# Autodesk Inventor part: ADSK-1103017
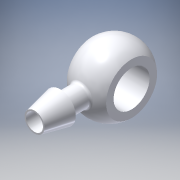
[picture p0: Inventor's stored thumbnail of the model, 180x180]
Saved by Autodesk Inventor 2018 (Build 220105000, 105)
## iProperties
Shininess: 50.0
Length Units: 11272
Angle Units: 11279
Time Units: 11290
Mass Units: 11286
Length Display Precision: 4
Angle Display Precision: 2
Compacted: True
Created: 2000-09
Part Number: ADSK-1103017
Document SubType Name: Modeling
Description: AIR INTAKE
Mass: 0.433217 g
Surface Area: 3.22275 cm^2
Volume: 0.159859 cm^3
Density: 2.71 g/cm^3
Material: Aluminum-6061
Appearance: Aluminum - Flat
Density: 0.0
Volumn: 0.0
Area: 0.0
PropertySet Name: Model Information
Control State: 0
Master: False
Checked Out: False
Author: Autodesk, Inc.
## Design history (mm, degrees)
node "Revolution1" dims "d5" = 90 deg
  sketch "Sketch2"
    geometry: L1 (-0.521, -2.783)-(-5.347, -2.783); L2 (-5.347, -2.783)-(-5.347, 0.351); L3 (-0.521, -2.783)-(-0.521, 0.351); A1 r 3.429 centre (-2.934, -2.085) between (-0.521, 0.351) and (-5.347, 0.351); 1 further point
    constraints: 6 end point, 2 parallel, 2 point on circle, 1 centre point, 1 horizontal, 1 midpoint, 1 perpendicular, 1 vertical alignment
    dimensions: "d2" = 4.1275 dimension on A1 L1; "d3" = 4.826 distance of L1.start L1.end; "d4" = 3.429 radius of A1
workaxis "Work Axis1"
workplane "Work Plane1"
node "Extrusion4" dims "d17" = 0, "d18" = 6.35
  sketch "Sketch6"
    geometry: C1 r 1.27 at (1.587, 1.923); 1 further point
    constraints: 1 centre point, 1 coincident
    dimensions: "d19" = 2.54 diameter of C1
node "Extrusion5" dims "d20" = -12 deg, "d21" = 3.175
  sketch "Sketch7"
    geometry: C1 r 1.27 at (0, 0) reference; C2 r 1.905 at (0, 0)
    constraints: 1 centre point, 1 coincident
    dimensions: "d22" = 3.81 diameter of C2
node "Extrusion6" dims "d23" = 0, "d24" = 10.795
  sketch "Sketch8"
    geometry: C1 r 1.23 at (0, 0) reference; C2 r 1.048 at (0, 0)
    constraints: 1 centre point, 1 coincident
    dimensions: "d25" = 2.0955 diameter of C2
node "Fillet2" dims "d26" = 0.381
node "Extrusion7" dims "d27" = 25.4, "d28" = 0
  sketch "Sketch9"
    geometry: C1 r 3.135 at (0, 0) reference; C2 r 2.212 at (0, 0)
    constraints: 1 centre point, 1 coincident
body "Solid1"
other parameters: "d6" = 90 deg
